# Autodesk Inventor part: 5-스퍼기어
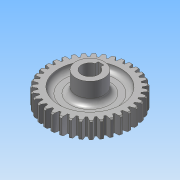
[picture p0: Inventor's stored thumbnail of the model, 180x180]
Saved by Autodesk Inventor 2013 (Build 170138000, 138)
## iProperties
Created: 2013-08
Part Number: 5-스퍼기어
Material: 강
Document SubType Name: Modeling
Designer: 한국산업디자인학원
Categories: <?xml version="1.0" encoding="UTF-16"?> <MemberInstance><Categories><FamilyTemplate><FamilyTemplateParameter ValueType="xs:double" Id="1" ObjectReferenceKey="da
Density: 1 g/cm^3
CustomPartVersion: 1
Author: 한국산업디자인학원
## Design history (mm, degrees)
sketch "Sketch1"
  geometry: C1 r 37 at (0, 0)
  constraints: 1 centre point
  dimensions: "d0" = 74 diameter of C1 (= da_da)
extrude "Extrusion1" new body sketch "Sketch1" distance "d1" = 15 (= da_b); taper "d2" = 0 deg
chamfer "모따기1" distance "d49" = 1; stored, may be unused: second distance "d50" = 2, angle "d51" = 45 deg
workplane "Work Plane2"
feature "피치 지름" dims "d4" = 10, "d5" = 0
workplane "Work Plane8"
workplane "Work Plane9"
feature "스퍼 기어" dims "da_b" = 15, "da_d" = 70, "da_aw" = 70, "da_da" = 74, "da_df" = 65, "da_dw" = 70, angle "da_beta" = 0 deg, "da_lefttooth" = 0, "da_righttooth" = 0
sketch "스케치3"
  geometry: C1 r 27.5 at (0, 0); A1 r 36 centre (0, 0) between (-5.215, 35.62) and (-7.633, 35.181) reference
  constraints: 1 centre point, 1 coincident
  dimensions: "d52" = 55 diameter of C1
extrude "돌출2" cut sketch "스케치3" distance "d54" = 5; taper "d55" = 0 deg
sketch "스케치4"
  geometry: C1 r 27.5 at (0, 0); A1 r 32.5 centre (0, 0) between (9.347, 31.127) and (7.941, 31.515) reference
  constraints: 1 centre point, 1 coincident
  dimensions: "d56" = 55 diameter of C1
extrude "돌출3" cut sketch "스케치4" distance "d58" = 5; taper "d59" = 0 deg
node "작업 평면11"
sketch "스케치5"
  geometry: C1 r 12.5 at (0, 0); 1 further point
  constraints: 1 centre point, 1 coincident
  dimensions: "d61" = 25 diameter of C1
extrude "돌출4" join sketch "스케치5" distance "d63" = 31; taper "d64" = 0 deg
sketch "스케치6"
  geometry: L1 (-2.5, 7.071)-(-2.5, 9.8); L2 (-2.5, 9.8)-(2.5, 9.8); L3 (2.5, 9.8)-(2.5, 7.071); C1 r 12.5 at (0, 0) reference; A1 r 7.5 centre (0, 0) between (-2.5, 7.071) and (2.5, 7.071); 1 further point
  constraints: 6 end point, 2 point on circle, 1 centre point, 1 coincident, 1 midpoint, 1 parallel, 1 perpendicular, 1 vertical, 1 vertical alignment
  dimensions: "d65" = 15 diameter of A1; "d67" = 5 distance of L1.end L2.end; "d68" = 17.3 dimension on A1 L2
extrude "돌출5" cut sketch "스케치6" stored distance "d69" = 31; taper "d70" = 0 deg
fillet "모깎기1" dims "d71" = 5
body "Solid1"
sketch "Sketch2"
  geometry: C1 r 37 at (0, 0) reference; C2 r 35 at (0, 0)
  constraints: 1 centre point, 1 coincident
  dimensions: "d3" = 70 diameter of C2 (= da_dw)
body "Srf1"
other parameters: "d17" = 0, "d34" = 0.8976 (computed from da_z), "d39" = 0, "d41" = 0, "d47" = 0, "d48" = 0, "d60" = 3
